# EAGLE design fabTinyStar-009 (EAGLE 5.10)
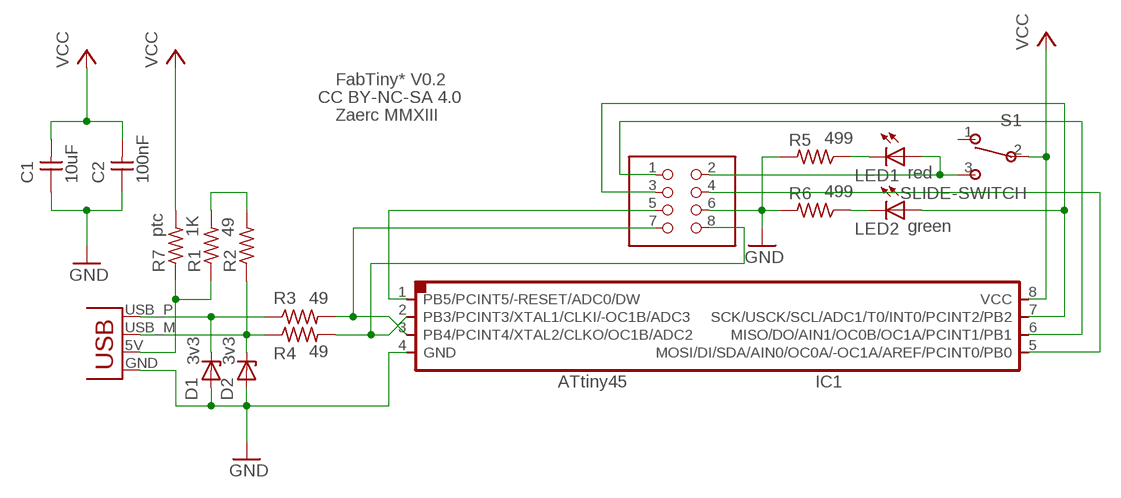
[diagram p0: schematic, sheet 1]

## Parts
C1  10uF  UNPOLARIZED_CAPACITOR1206  [1206]
C2  100nF  UNPOLARIZED_CAPACITOR1206  [1206]
D1  3v3  ZENER_DIODESOD123  [SOD123]
D2  3v3  ZENER_DIODESOD123  [SOD123]
IC1  ATTINY*5  ATTINY45SI  [SOIC8]
JP1  PINHD-2X04  [54202-G0808LF]
LED1  red  LEDSMT1206  [1206]
LED2  green  LEDSMT1206  [1206]
R1  1K  RESISTOR1206  [1206]
R2  49  RESISTOR1206  [1206]
R3  49  RESISTOR1206  [1206]
R4  49  RESISTOR1206  [1206]
R5  499  RESISTOR1206  [1206]
R6  499  RESISTOR1206  [1206]
R7  ptc  RESISTOR1206  [1206]
S1  SLIDE-SWITCH  [AYZ0102AGRLC]
USB  USBPCB  [USB-A-PCB]

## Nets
5V: R1.1 R7.1 USB.5V(VBUS)
B0: IC1.5(MOSI/DI/SDA/AIN0/OC0A/-OC1A/AREF/PCINT0/PB0) JP1.4
B1: IC1.6(MISO/DO/AIN1/OC0B/OC1A/PCINT1/PB1) JP1.1
B2: IC1.7(SCK/USCK/SCL/ADC1/T0/INT0/PCINT2/PB2) JP1.3 LED2.A
B3: IC1.2(PB3/PCINT3/XTAL1/CLKI/-OC1B/ADC3) JP1.8 R4.2
B4: IC1.3(PB4/PCINT4/XTAL2/CLKO/OC1B/ADC2) JP1.7 R3.2
B5: IC1.1(PB5/PCINT5/-RESET/ADC0/DW) JP1.5
D+: D1.CATHODE R3.1 USB.USB_P(D+)
D-: D2.CATHODE R2.1 R4.1 USB.USB_M(D-)
GND: C1.1 C2.1 D1.ANODE D2.ANODE IC1.4(GND) JP1.6 R5.2 R6.2 USB.GND
N$1: R1.2 R2.2
N$13: LED2.C R6.1
N$14: LED1.C R5.1
TP: JP1.2 LED1.A S1.3
VCC: C1.2 C2.2 IC1.8(VCC) R7.2 S1.2
Unconnected: S1.1

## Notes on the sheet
- FabTiny* V0.2
- CC BY-NC-SA 4.0
- Zaerc MMXIII

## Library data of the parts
C1 C2 = 01_FAB_Hello:UNPOLARIZED_CAPACITOR: unpolarized_capacitor
D1 D2 = 01_fab:ZENER_DIODE: zener diode
IC1 = 01_fab:ATTINY45
JP1 = Zaerc:PINHD-2X04
LED1 LED2 = led:LED: LED
R1-R7 = 01_FAB_Hello:RESISTOR
S1 = Zaerc:SLIDE-SWITCH
USB = SparkFun:USB: USB Connectors USB-B-PTH is fully proven SKU : PRT-00139 USB-miniB is fully proven SKU : PRT-00587 USB-A-PCB is untested. USB-A-H is throughly reviewed, but untested. Spark Fun Electronics SKU : PRT-00437 USB-B-SMT is throughly reviewed, but untested. Needs silkscreen touching up. USB-A-S has not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

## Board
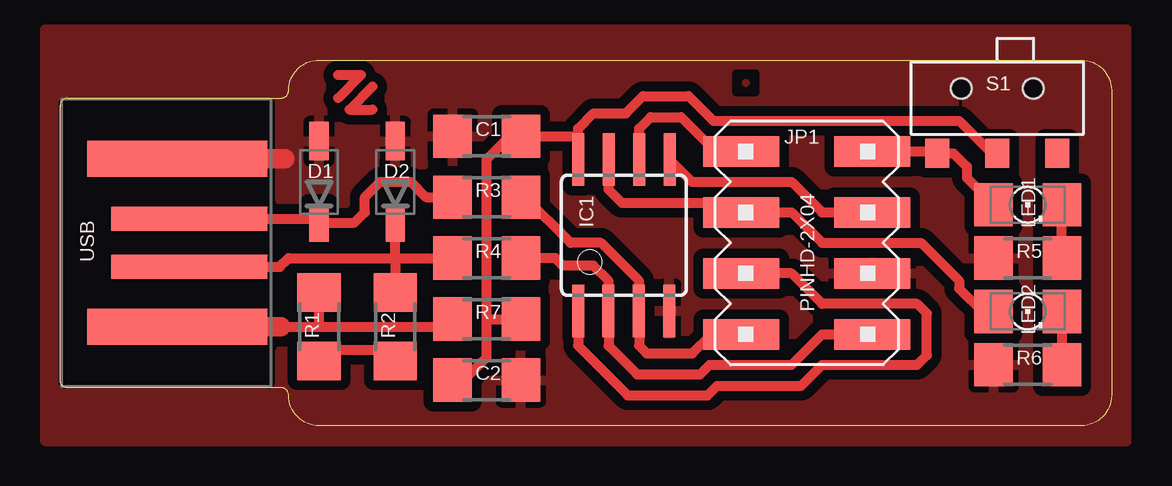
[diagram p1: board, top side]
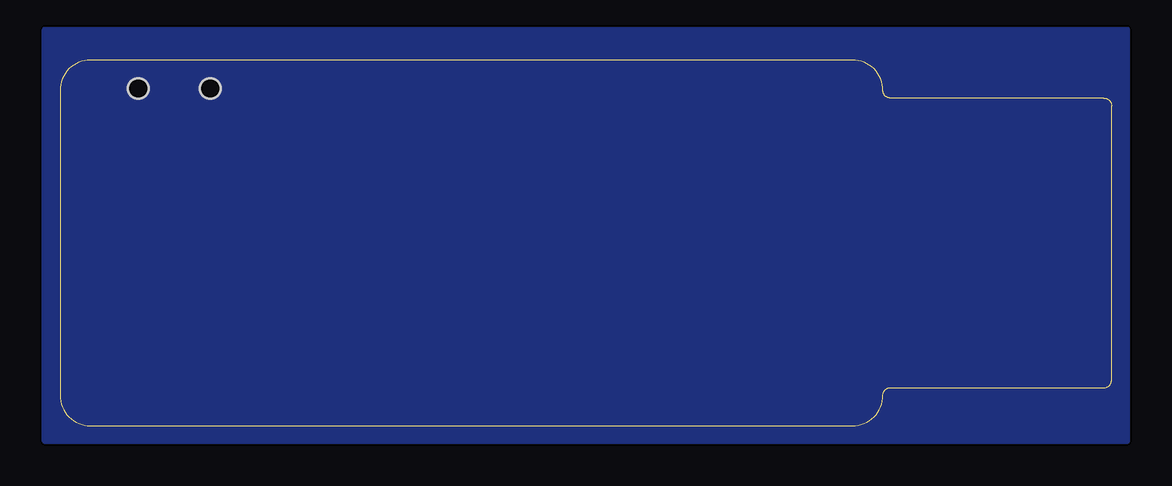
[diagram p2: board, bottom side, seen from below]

Size 43.81 x 15.24 mm. Coordinates in mm from the lower left corner, seen from the top.
Outline: 9.21,13.65 arc90 9.53,13.97 arc-90 10.79,15.24 42.55,15.24 arc-90 43.81,13.97 43.81,1.27 arc-90 42.55,0 10.79,0 arc-90 9.53,1.27 arc90 9.21,1.59 0.32,1.59 arc-90 0,1.91 0,13.34 arc-90 0.32,13.65 9.21,13.65
Copper layers (1*16): Top 0.035mm / dielectric 1.5mm / Bottom 0.035mm
Design rules "default *": minimum track width 10mil, minimum drill 24mil, track to track 16mil, track to pad 16mil, pad to pad 16mil, via to via 16mil, smd to smd 8mil, copper to edge 0mil, drill to drill 8mil, minimum pad ring 10mil, minimum via ring 8mil, stop-mask expansion 4mil, vias tented up to drill 0mil, thermal gap 10mil
tRestrict: area 0.2,1.7 to 8.7,13.5

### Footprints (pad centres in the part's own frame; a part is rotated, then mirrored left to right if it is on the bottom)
1206 = smd 1.6 x 1.803: 1 -1.422,0; 2 1.422,0
SOD123 = smd 1.6 x 0.8: ANODE 1.7,0; CATHODE -1.7,0
SOIC8 = smd 0.5 x 2.2: 1 -1.905,-3.154; 2 -0.645,-3.154; 3 0.625,-3.154; 4 1.895,-3.154; 5 1.905,3.154; 6 0.635,3.154; 7 -0.635,3.154; 8 -1.905,3.154
54202-G0808LF = smd 1.27 x 3.175: 1 -3.81,-2.731; 2 -3.81,2.731; 3 -1.27,-2.731; 4 -1.27,2.731; 5 1.27,-2.731; 6 1.27,2.731; 7 3.81,-2.731; 8 3.81,2.731
1206' = smd 1.6 x 1.803: A -1.422,0; C 1.422,0
AYZ0102AGRLC = smd 1 x 1.2: 1 2.5,-2.3; 2 0,-2.3; 3 -2.5,-2.3 | hole 0.85: -1.5,0.4; 1.5,0.4
USB-A-PCB = smd 7.5 x 1.5: 5V -0.2,-3.5; GND -0.2,3.5 | smd 6.5 x 1: USB_M 0.3,-1; USB_P 0.3,1

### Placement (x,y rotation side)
C1  17.78,12.06 0 top
C2  17.78,1.91 180 top
D1  10.79,10.16 90 top
D2  13.97,10.16 90 top
IC1  23.5,7.94 0 top
JP1  31.11,7.62 270 top
LED1  red  [1206']  40.32,9.21 0 top
LED2  green  [1206']  40.32,4.76 0 top
R1  10.79,4.13 270 top
R2  13.97,4.13 270 top
R3  17.78,9.53 0 top
R4  17.78,6.99 0 top
R5  40.32,6.99 180 top
R6  40.32,2.54 180 top
R7  17.78,4.45 0 top
S1  39.05,13.65 0 top
USB  5.08,7.62 0 top

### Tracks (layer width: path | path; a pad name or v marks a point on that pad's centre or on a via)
5V
  Top 0.406: 10.79,4.12 16.03,4.12 R7.1 | 10.79,4.12 R1.1 | 9.2,4.12 10.79,4.12
  Top 0.813: USB.5V 9.2,4.12
B0
  Top 0.406: JP1.4 31.75,8.89 30.48,10.16 26.33,10.16 IC1.5
B1
  Top 0.406: JP1.1 27.3,11.43 25.88,12.86 24.61,12.86 24.13,12.38 IC1.6
B2
  Top 0.406: IC1.7 22.86,9.84 23.42,9.29 27.86,9.29 28.26,8.89 JP1.3 30.48,8.89 31.75,7.62 35.88,7.62 37.47,6.03 37.47,5.71 38.42,4.76 LED2.A
B3
  Top 0.406: JP1.8 31.75,3.81 30.48,2.54 27.07,2.54 26.67,2.14 24.05,2.14 22.86,3.33 IC1.2 | R4.2 20.64,6.99 20.95,6.67 22.23,6.67 22.86,6.03 IC1.2 | IC1.2
B4
  Top 0.406: JP1.7 27.15,3.81 26.35,3.02 24.45,3.02 24.13,3.33 IC1.3 | IC1.3 | IC1.3 24.13,6.03 22.54,7.62 21.27,7.62 19.37,9.53 R3.2
B5
  Top 0.406: IC1.1 21.59,3.33 23.65,1.27 26.99,1.27 27.38,1.67 30.88,1.67 31.75,2.54 35.72,2.54 36.12,2.94 36.12,4.68 35.72,5.08 31.75,5.08 30.48,6.35 JP1.5
D+
  Top 0.406: USB.USB_P 10.63,8.62 D1.CATHODE 12.27,8.46 12.7,8.89 12.7,9.53 13.34,10.16 14.61,10.16 15.24,9.53 R3.1
D-
  Top 0.406: 13.97,6.99 D2.CATHODE | USB.USB_M 9.16,6.62 9.53,6.99 13.97,6.99 | 13.97,6.99 R2.1 | 13.97,6.99 R4.1
GND
  Top 0.813: USB.GND 9.37,11.12
  pour Top (rank 6): -0.64,-0.64 44.45,-0.64 44.45,16.51 -0.64,16.51
N$1
  Top 0.406: R1.2 10.79,3.17 13.97,3.17 R2.2
N$2
  pour Bottom: -0.64,-0.64 44.45,-0.64 44.45,16.51 -0.64,16.51
N$3
  pour Top: 28.57,14.13 28.58,14.13 arc90 28.73,14.29 arc90 28.57,14.45 arc90 28.42,14.29 28.42,14.29 arc90
N$13
  Top 0.406: LED2.C R6.1
N$14
  Top 0.406: R5.1 LED1.C
N$33
  Top 0.406: 11.59,14.61 12.54,14.61 11.59,13.65
N$34
  Top 0.406: 13.02,14.13 12.06,13.18 13.02,13.18
TP
  Top 0.406: JP1.2 36.48,11.43 S1.3 37.23,11.35 37.78,10.79 37.78,10.32 LED1.A
VCC
  Top 0.406: 17.78,4.45 R7.2 | 17.78,4.45 17.78,11.11 18.73,12.06 C1.2 21.59,12.06 | 21.59,12.06 IC1.8 | 21.59,12.06 21.59,12.38 22.23,13.02 23.57,13.02 24.29,13.73 26.19,13.73 27.23,12.7 37.47,12.7 38.73,11.43 38.98,11.43 S1.2 | C2.2 16.83,1.91 17.78,2.86 17.78,4.45

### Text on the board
tDocu: FabTiny* v0.2 | CC BY-NC-SA 4.0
